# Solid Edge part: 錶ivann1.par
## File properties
Author: KULL
Template: Iso Metric Part.par
Last saved by: KULL
Revision: 18
Application: Solid Edge
Accuracy: 0,990
Face Style: Model Default
Fill Style: Normal
Coef. of Thermal Exp: 0.0
Thermal Conductivity: 0.0
Specific Heat: 0.0
Modulus of Elasticity: 0.0
Poisson's Ratio: 0.0
Yield Stress: 0.0
Ultimate Stress: 0.0
Elongation: 0.0
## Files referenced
..\Mootor_ASM_1.asm
ikkega.par
lG:\Haapsalu Kolledz\Solid edge leong\Solid edge Sync practice\ROVER_Heiko_Kull_EKSAM\Mootor\Mootor_ASM_1.asm
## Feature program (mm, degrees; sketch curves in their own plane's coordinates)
sketch for "Hole_2" plane through (0, 0, 1.8435) normal (0, 0, -1) x-axis (0, -1, 0)
  hole centre (18.6197, 33.7) bore radius 0.7
hole "Hole_2" diameter 1.4 finite
sketch for "unnamed Hole 1" plane through (0, 0, 1.8435) normal (0, 0, -1) x-axis (0, -1, 0)
  hole centre (18.6197, 18) bore radius 0.7
hole "unnamed Hole 1" finite
sketch for "unnamed Hole 2" plane through (0, 0, 1.8435) normal (0, 0, -1) x-axis (0, -1, 0)
  hole centre (18.6197, 0) bore radius 0.7
hole "unnamed Hole 2" finite
sketch for "unnamed Hole 3" plane through (0, 0, 1.8435) normal (0, 0, -1) x-axis (0, -1, 0)
  hole centre (18.6197, -18) bore radius 0.7
hole "unnamed Hole 3" finite
sketch for "unnamed Hole 4" plane through (0, 0, 1.8435) normal (0, 0, -1) x-axis (0, -1, 0)
  hole centre (18.6197, -33.7) bore radius 0.7
hole "unnamed Hole 4" finite
sketch for "unnamed Hole 5" plane through (0, 0, 1.8435) normal (0, 0, -1) x-axis (0, -1, 0)
  hole centre (-18.6197, 33.7) bore radius 0.7
hole "unnamed Hole 5" finite
sketch for "unnamed Hole 6" plane through (0, 0, 1.8435) normal (0, 0, -1) x-axis (0, -1, 0)
  hole centre (-18.6197, 0) bore radius 0.7
hole "unnamed Hole 6" finite
sketch for "unnamed Hole 7" plane through (0, 0, 1.8435) normal (0, 0, -1) x-axis (0, -1, 0)
  hole centre (-18.6197, -18) bore radius 0.7
hole "unnamed Hole 7" finite
sketch for "unnamed Hole 8" plane through (0, 0, 1.8435) normal (0, 0, -1) x-axis (0, -1, 0)
  hole centre (-18.6197, -33.7) bore radius 0.7
hole "unnamed Hole 8" finite
pattern "unnamed Pattern 1" of "Hole_2", "unnamed Hole 1", "unnamed Hole 2", "unnamed Hole 3", "unnamed Hole 4", "unnamed Hole 5", "unnamed Hole 6", "unnamed Hole 7", "unnamed Hole 8"
sketch for "Hole_11" plane through (0, 0, 1.8435) normal (0, 0, -1) x-axis (0, -1, 0)
  hole centre (-18.6197, 18) bore radius 0.7
hole "Hole_11" diameter 1.4 finite
pattern "unnamed Pattern 2" of "Hole_11"
sketch for "Hole_12" plane through (45.469, -8.3485, 1.0232) normal (0, 0, -1) x-axis (1, 0, 0)
  hole centre (-0.069, 0) bore radius 0.7
hole "Hole_12" diameter 1.4 finite
sketch for "unnamed Hole 9" plane through (45.469, 0, 1.0232) normal (0, 0, -1) x-axis (1, 0, 0)
  hole centre (-0.069, 0) bore radius 0.7
hole "unnamed Hole 9" finite
sketch for "unnamed Hole 10" plane through (45.4631, 0, 1.0232) normal (0, 0, -1) x-axis (0, 1, 0)
  hole centre (8.3485, -0.0631) bore radius 0.7
hole "unnamed Hole 10" finite
sketch for "unnamed Hole 11" plane through (45.4631, 0, 1.0232) normal (0, 0, -1) x-axis (0, 1, 0)
  hole centre (-8.3485, -90.8631) bore radius 0.7
hole "unnamed Hole 11" finite
sketch for "unnamed Hole 12" plane through (45.4631, 0, 1.0232) normal (0, 0, -1) x-axis (0, 1, 0)
  hole centre (0, -90.8631) bore radius 0.7
hole "unnamed Hole 12" finite
sketch for "unnamed Hole 13" plane through (45.4631, 0, 1.0232) normal (0, 0, -1) x-axis (0, 1, 0)
  hole centre (8.3485, -90.8631) bore radius 0.7
hole "unnamed Hole 13" finite
pattern "unnamed Pattern 3" of "Hole_12", "unnamed Hole 9", "unnamed Hole 10", "unnamed Hole 11", "unnamed Hole 12", "unnamed Hole 13"
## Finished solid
Body 1: sheet body, 1 face, 66 edges, 56 vertices.
  Faces by surface: plane 1
  Edges by curve: intersection 24, circle 20, line 18, ellipse 4
Body 2: sheet body, 1 face, 74 edges, 68 vertices.
  Faces by surface: plane 1
  Edges by curve: line 26, circle 20, ellipse 20, intersection 4, spline 4
Body 3: solid body, 399 faces, 922 edges, 514 vertices.
  Faces by surface: cylinder 156, blend 102, torus 72, plane 57, swept 8, offset 4
  Edges by curve: circle 432, line 276, intersection 147, ellipse 59, spline 8
Bounding box of the edges (mm; curved faces can reach further): 96.000 x 40.839 x 11.500, from (-48, -20.4197, -7.8565) to (48, 20.4197, 3.6435).
Cylindrical faces by radius (mm): R0.05 x14, R0.2 x32, R0.6 x30, R0.7 x16, R1 x4, R1.4 x16, R1.6 x4, R1.8 x10, R2 x4, R2.1 x1, R2.5 x1, R2.6 x2, R3 x6, R3.4 x4, R3.6 x4, R4 x4, R9.6 x2, R10 x2
Toroidal faces (ring radius, tube radius in mm): R0.65 r0.05 x20, R0.8 r0.2 x20, R1.2 r0.2 x6, R1.6 r0.2 x16, R1.75 r0.05 x10
Planar faces by outward normal: +x 6, +y 8, +z 4, -x 6, -y 8, -z 9, oblique 16
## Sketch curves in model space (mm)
arc centre (-45.4, 8.3485, 3.6435) radius 1.4 from (-45.225, 6.9594, 3.6435) through (-44.0009, 8.2981, 3.6435) to (-45.0455, 9.7028, 3.6435)
arc centre (-45.4, 0, 3.6435) radius 1.4 from (-45.225, -1.389, 3.6435) through (-44.0024, 0.0826, 3.6435) to (-45.225, 1.389, 3.6435)
arc centre (-45.4, -8.3485, 3.6435) radius 1.4 from (-45.0455, -9.7028, 3.6435) through (-44.0063, -8.2161, 3.6435) to (-45.225, -6.9594, 3.6435)
arc centre (45.4, 0, 3.6435) radius 1.4 from (45.225, 1.389, 3.6435) through (44.0024, -0.0826, 3.6435) to (45.225, -1.389, 3.6435)
arc centre (45.4, 8.3485, 3.6435) radius 1.4 from (45.0455, 9.7028, 3.6435) through (44.0063, 8.2161, 3.6435) to (45.225, 6.9594, 3.6435)
arc centre (45.4, -8.3485, 3.6435) radius 1.4 from (45.225, -6.9594, 3.6435) through (44.0009, -8.2981, 3.6435) to (45.0455, -9.7028, 3.6435)
circle centre (-33.7, 18.6197, 1.8435) radius 0.7
circle centre (0, 18.6197, 1.8435) radius 0.7
circle centre (18, 18.6197, 1.8435) radius 0.7
circle centre (33.7, 18.6197, 1.8435) radius 0.7
circle centre (33.7, -18.6197, 1.8435) radius 0.7
circle centre (18, -18.6197, 1.8435) radius 0.7
circle centre (0, -18.6197, 1.8435) radius 0.7
circle centre (-18, -18.6197, 1.8435) radius 0.7
circle centre (-33.7, -18.6197, 1.8435) radius 0.7
arc centre (0, -18.6197, 2.6435) radius 1.5 from (-1.5, -18.6197, 2.6435) through (0.0444, -20.119, 2.6435) to (1.5, -18.6197, 2.6435)
arc centre (-33.7, 18.6197, 0) radius 1.5 from (-32.2, 18.6197, 0) through (-33.7444, 20.119, 0) to (-35.2, 18.6197, 0)
line (-35.2, -18.6197, 0) -> (-32.2, -18.6197, 0)
arc centre (-33.7, -18.6197, 0) radius 1.5 from (-35.2, -18.6197, 0) through (-33.6556, -20.119, 0) to (-32.2, -18.6197, 0)
line (-19.5, 18.6197, 0) -> (-16.5, 18.6197, 0)
arc centre (-18, 18.6197, 0) radius 1.5 from (-16.5, 18.6197, 0) through (-18.0444, 20.119, 0) to (-19.5, 18.6197, 0)
line (-1.5, 18.6197, 0) -> (1.5, 18.6197, 0)
arc centre (0, 18.6197, 0) radius 1.5 from (1.5, 18.6197, 0) through (-0.0444, 20.119, 0) to (-1.5, 18.6197, 0)
line (16.5, 18.6197, 0) -> (19.5, 18.6197, 0)
arc centre (18, 18.6197, 0) radius 1.5 from (19.5, 18.6197, 0) through (17.9556, 20.119, 0) to (16.5, 18.6197, 0)
line (32.2, 18.6197, 0) -> (35.2, 18.6197, 0)
arc centre (33.7, 18.6197, 0) radius 1.5 from (35.2, 18.6197, 0) through (33.6556, 20.119, 0) to (32.2, 18.6197, 0)
line (32.2, -18.6197, 0) -> (35.2, -18.6197, 0)
arc centre (33.7, -18.6197, 0) radius 1.5 from (32.2, -18.6197, 0) through (33.7444, -20.119, 0) to (35.2, -18.6197, 0)
line (16.5, -18.6197, 0) -> (19.5, -18.6197, 0)
arc centre (18, -18.6197, 0) radius 1.5 from (16.5, -18.6197, 0) through (18.0444, -20.119, 0) to (19.5, -18.6197, 0)
line (-1.5, -18.6197, 0) -> (1.5, -18.6197, 0)
arc centre (0, -18.6197, 0) radius 1.5 from (-1.5, -18.6197, 0) through (0.0444, -20.119, 0) to (1.5, -18.6197, 0)
line (-19.5, -18.6197, 0) -> (-16.5, -18.6197, 0)
arc centre (-18, -18.6197, 0) radius 1.5 from (-19.5, -18.6197, 0) through (-17.9556, -20.119, 0) to (-16.5, -18.6197, 0)
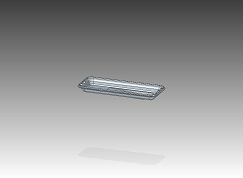
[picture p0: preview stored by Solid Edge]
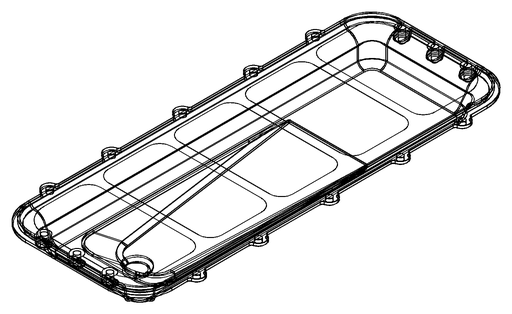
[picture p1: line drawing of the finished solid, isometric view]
